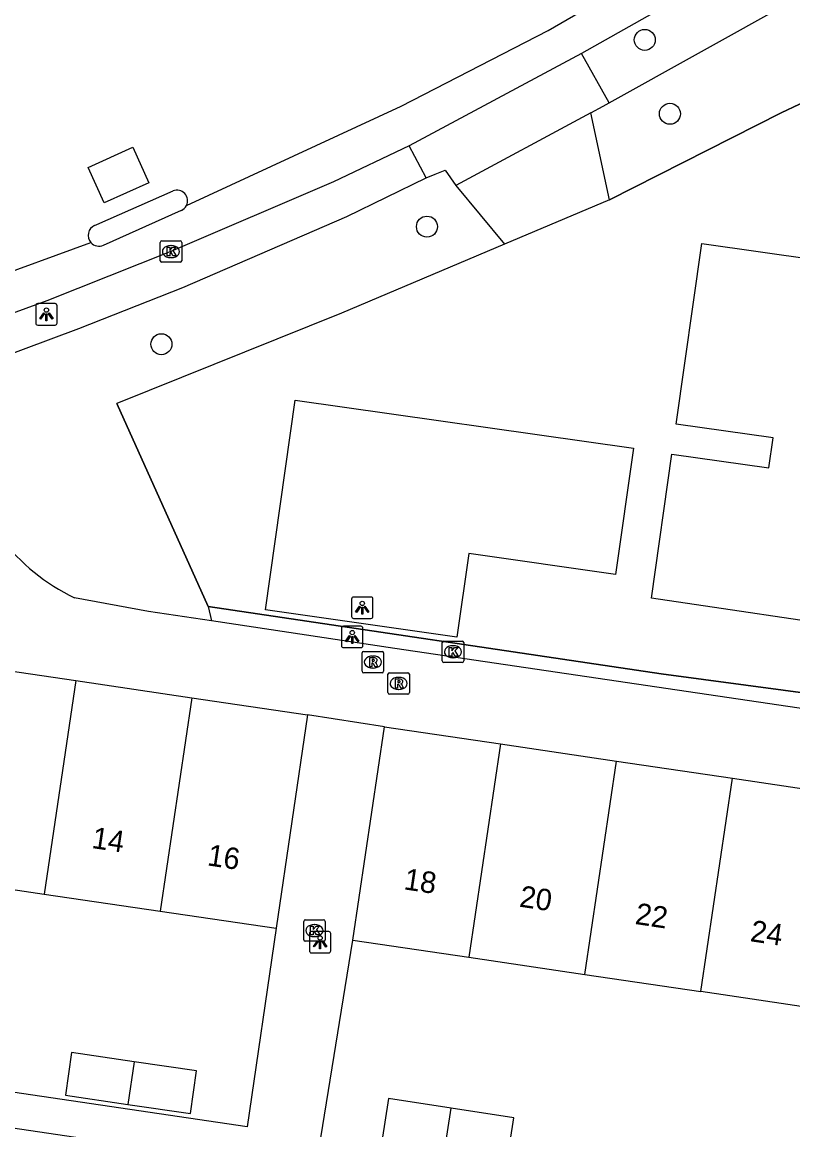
# Model space of a CAD drawing. Extents: x 164150 to 165261, y 382513 to 383432.
# Drawn here: x 164416.6 to 164452.5, y 383340.9 to 383392.6 of the extents above; entities that cross this region are included whole.
import ezdxf

# ---------------------------------------------------------------- set-up
doc = ezdxf.new("R2010")
doc.units = 0
for name, color, linetype in [('IMGEO_Boom', 7, 'Continuous'), ('IMGEO_Groenvoorziening', 7, 'Continuous'), ('IMGEO_Hek', 7, 'Continuous'), ('IMGEO_Kolk', 7, 'Continuous'), ('IMGEO_Lichtpunt', 7, 'Continuous'), ('IMGEO_Pand', 7, 'Continuous'), ('IMGEO_Pand_nummerreeks', 7, 'Continuous'), ('IMGEO_Rijbaan_lokaal_gesloten', 7, 'Continuous'), ('IMGEO_Rioolput', 7, 'Continuous'), ('IMGEO_Voetpad_open', 7, 'Continuous')]:
    doc.layers.add(name, color=color, linetype=linetype)

msp = doc.modelspace()

# ---------------------------------------------------------------- linework, layer by layer
at = {"layer": 'IMGEO_Boom'}
for centre in [(164445.636, 383391.73), (164446.809, 383388.287), (164435.49, 383383.028), (164423.12, 383377.55)]:
    msp.add_circle(centre, 0.489, dxfattribs=at)
at = {"layer": 'IMGEO_Groenvoorziening'}
for points in [[(164495.205, 383395.312), (164485.846, 383406.541), (164475.669, 383398.705), (164457.962, 383391.157), (164451.983, 383388.33), (164443.993, 383384.279)], [(164439.097, 383382.204), (164431.513, 383378.99), (164421.044, 383374.785), (164425.292, 383365.326)], [(164425.292, 383365.326), (164446.405, 383362.194), (164456.026, 383360.895), (164526.656, 383350.3)], [(164425.292, 383365.326), (164425.46, 383364.655)]]:
    msp.add_lwpolyline(points, dxfattribs=at)
at = {"layer": 'IMGEO_Hek'}
for points in [[(164443.993, 383384.279), (164451.983, 383388.33), (164457.962, 383391.157), (164475.669, 383398.705), (164485.846, 383406.541)], [(164439.097, 383382.204), (164431.513, 383378.99)], [(164431.513, 383378.99), (164421.044, 383374.785)], [(164425.292, 383365.326), (164421.044, 383374.785)], [(164526.656, 383350.3), (164456.026, 383360.895), (164446.405, 383362.194), (164425.292, 383365.326)]]:
    msp.add_lwpolyline(points, dxfattribs=at)
at = {"layer": 'IMGEO_Kolk'}
for p, q in [((164423.064, 383381.441), (164423.064, 383382.293)), ((164423.139, 383382.367), (164423.991, 383382.367)), ((164423.552, 383382.147), (164423.577, 383382.147)), ((164424.065, 383382.293), (164424.065, 383381.441)), ((164423.575, 383381.587), (164423.55, 383381.587)), ((164423.991, 383381.367), (164423.139, 383381.367)), ((164436.202, 383362.793), (164436.202, 383363.645)), ((164436.277, 383363.719), (164437.129, 383363.719)), ((164436.69, 383363.499), (164436.715, 383363.499)), ((164437.203, 383363.645), (164437.203, 383362.793)), ((164436.713, 383362.939), (164436.688, 383362.939)), ((164437.129, 383362.719), (164436.277, 383362.719)), ((164429.748, 383349.803), (164429.748, 383350.655)), ((164429.823, 383350.729), (164430.675, 383350.729)), ((164430.236, 383350.509), (164430.261, 383350.509)), ((164430.749, 383350.655), (164430.749, 383349.803)), ((164430.259, 383349.949), (164430.234, 383349.949)), ((164430.675, 383349.729), (164429.823, 383349.729))]:
    msp.add_line(p, q, dxfattribs=at)
for points in [[(164423.064, 383381.441), (164423.064, 383382.293)], [(164423.139, 383382.367), (164423.991, 383382.367)], [(164423.385, 383382.067), (164423.508, 383382.067), (164423.508, 383381.916), (164423.638, 383382.067), (164423.802, 383382.067), (164423.656, 383381.916), (164423.809, 383381.667), (164423.657, 383381.667), (164423.572, 383381.831), (164423.508, 383381.764), (164423.508, 383381.667), (164423.385, 383381.667), (164423.385, 383382.067)], [(164424.065, 383382.293), (164424.065, 383381.441)], [(164423.991, 383381.367), (164423.139, 383381.367)], [(164436.202, 383362.793), (164436.202, 383363.645)], [(164436.277, 383363.719), (164437.129, 383363.719)], [(164436.523, 383363.419), (164436.646, 383363.419), (164436.646, 383363.268), (164436.776, 383363.419), (164436.94, 383363.419), (164436.794, 383363.268), (164436.947, 383363.019), (164436.795, 383363.019), (164436.71, 383363.183), (164436.646, 383363.116), (164436.646, 383363.019), (164436.523, 383363.019), (164436.523, 383363.419)], [(164437.203, 383363.645), (164437.203, 383362.793)], [(164437.129, 383362.719), (164436.277, 383362.719)], [(164429.748, 383349.803), (164429.748, 383350.655)], [(164429.823, 383350.729), (164430.675, 383350.729)], [(164430.749, 383350.655), (164430.749, 383349.803)], [(164430.069, 383350.429), (164430.192, 383350.429), (164430.192, 383350.278), (164430.322, 383350.429), (164430.486, 383350.429), (164430.34, 383350.278), (164430.493, 383350.029), (164430.341, 383350.029), (164430.256, 383350.193), (164430.192, 383350.126), (164430.192, 383350.029), (164430.069, 383350.029), (164430.069, 383350.429)], [(164430.675, 383349.729), (164429.823, 383349.729)]]:
    msp.add_lwpolyline(points, dxfattribs=at)
for centre, start, end in [((164423.141, 383382.291), 91.552, 178.448), ((164423.141, 383382.291), 91.552, 178.448), ((164423.989, 383382.291), 1.552, 88.448), ((164423.989, 383382.291), 1.552, 88.448), ((164423.141, 383381.443), 181.552, 268.448), ((164423.141, 383381.443), 181.552, 268.448), ((164423.989, 383381.443), 271.552, 358.448), ((164423.989, 383381.443), 271.552, 358.448), ((164436.279, 383363.643), 91.552, 178.448), ((164436.279, 383363.643), 91.552, 178.448), ((164437.127, 383363.643), 1.552, 88.448), ((164437.127, 383363.643), 1.552, 88.448), ((164436.279, 383362.795), 181.552, 268.448), ((164436.279, 383362.795), 181.552, 268.448), ((164437.127, 383362.795), 271.552, 358.448), ((164437.127, 383362.795), 271.552, 358.448), ((164429.825, 383350.653), 91.552, 178.448), ((164429.825, 383350.653), 91.552, 178.448), ((164430.673, 383350.653), 1.552, 88.448), ((164430.673, 383350.653), 1.552, 88.448), ((164429.825, 383349.805), 181.552, 268.448), ((164429.825, 383349.805), 181.552, 268.448), ((164430.673, 383349.805), 271.552, 358.448), ((164430.673, 383349.805), 271.552, 358.448)]:
    msp.add_arc(centre, 0.0765, start, end, dxfattribs=at)
for centre, major_axis, ratio, start_param, end_param in [((164423.551, 383381.867), (-0.387, 0.002), 0.722429, 4.712389, 7.853982), ((164423.576, 383381.867), (-0.39, 0.002), 0.717154, 1.570796, 4.712389), ((164436.689, 383363.219), (-0.387, 0.002), 0.722429, 4.712389, 7.853982), ((164436.714, 383363.219), (-0.39, 0.002), 0.717154, 1.570796, 4.712389), ((164430.235, 383350.229), (-0.387, 0.002), 0.722429, 4.712389, 7.853982), ((164430.26, 383350.229), (-0.39, 0.002), 0.717154, 1.570796, 4.712389)]:
    msp.add_ellipse(centre, major_axis=major_axis, ratio=ratio, start_param=start_param, end_param=end_param, dxfattribs=at)
at = {"layer": 'IMGEO_Lichtpunt'}
for p, q in [((164417.264, 383379.344), (164417.264, 383378.537)), ((164417.264, 383379.344), (164417.264, 383378.537)), ((164418.166, 383379.439), (164417.358, 383379.439)), ((164418.166, 383379.439), (164417.358, 383379.439)), ((164418.26, 383378.537), (164418.26, 383379.344)), ((164418.26, 383378.537), (164418.26, 383379.344)), ((164417.358, 383378.443), (164418.166, 383378.443)), ((164417.358, 383378.443), (164418.166, 383378.443)), ((164431.977, 383365.674), (164431.977, 383364.867)), ((164431.977, 383365.674), (164431.977, 383364.867)), ((164432.879, 383365.769), (164432.071, 383365.769)), ((164432.879, 383365.769), (164432.071, 383365.769)), ((164432.973, 383364.867), (164432.973, 383365.674)), ((164432.973, 383364.867), (164432.973, 383365.674)), ((164432.412, 383364.409), (164431.604, 383364.409)), ((164432.412, 383364.409), (164431.604, 383364.409)), ((164432.071, 383364.773), (164432.879, 383364.773)), ((164432.071, 383364.773), (164432.879, 383364.773)), ((164431.51, 383364.314), (164431.51, 383363.507)), ((164431.51, 383364.314), (164431.51, 383363.507)), ((164432.506, 383363.507), (164432.506, 383364.314)), ((164432.506, 383363.507), (164432.506, 383364.314)), ((164431.604, 383363.413), (164432.412, 383363.413)), ((164431.604, 383363.413), (164432.412, 383363.413)), ((164430.015, 383350.09), (164430.015, 383349.283)), ((164430.015, 383350.09), (164430.015, 383349.283)), ((164430.917, 383350.185), (164430.109, 383350.185)), ((164430.917, 383350.185), (164430.109, 383350.185)), ((164431.011, 383349.283), (164431.011, 383350.09)), ((164431.011, 383349.283), (164431.011, 383350.09)), ((164430.109, 383349.189), (164430.917, 383349.189)), ((164430.109, 383349.189), (164430.917, 383349.189))]:
    msp.add_line(p, q, dxfattribs=at)
for points in [[(164417.638, 383379.008), (164417.677, 383378.98), (164417.489, 383378.718), (164417.451, 383378.745), (164417.638, 383379.008)], [(164417.74, 383378.96), (164417.787, 383378.96), (164417.787, 383378.638), (164417.74, 383378.638), (164417.74, 383378.96)], [(164417.85, 383378.98), (164417.888, 383379.007), (164418.075, 383378.745), (164418.036, 383378.717), (164417.85, 383378.98)], [(164432.351, 383365.338), (164432.39, 383365.31), (164432.202, 383365.048), (164432.164, 383365.075), (164432.351, 383365.338)], [(164432.453, 383365.29), (164432.5, 383365.29), (164432.5, 383364.968), (164432.453, 383364.968), (164432.453, 383365.29)], [(164432.563, 383365.31), (164432.601, 383365.337), (164432.788, 383365.075), (164432.749, 383365.047), (164432.563, 383365.31)], [(164431.884, 383363.978), (164431.923, 383363.95), (164431.735, 383363.688), (164431.697, 383363.715), (164431.884, 383363.978)], [(164431.986, 383363.93), (164432.033, 383363.93), (164432.033, 383363.608), (164431.986, 383363.608), (164431.986, 383363.93)], [(164432.096, 383363.95), (164432.134, 383363.977), (164432.321, 383363.715), (164432.282, 383363.687), (164432.096, 383363.95)], [(164430.389, 383349.754), (164430.428, 383349.726), (164430.24, 383349.464), (164430.202, 383349.491), (164430.389, 383349.754)], [(164430.491, 383349.706), (164430.538, 383349.706), (164430.538, 383349.384), (164430.491, 383349.384), (164430.491, 383349.706)], [(164430.601, 383349.726), (164430.639, 383349.753), (164430.826, 383349.491), (164430.787, 383349.463), (164430.601, 383349.726)]]:
    msp.add_lwpolyline(points, dxfattribs=at)
for centre in [(164417.763, 383379.142), (164432.476, 383365.472), (164432.009, 383364.112), (164430.514, 383349.888)]:
    msp.add_circle(centre, 0.0994, dxfattribs=at)
for centre, start, end in [((164417.358, 383379.344), 90, 180), ((164417.358, 383379.344), 90, 180), ((164418.166, 383379.344), 0, 90), ((164418.166, 383379.344), 0, 90), ((164417.358, 383378.537), 180, 270), ((164417.358, 383378.537), 180, 270), ((164418.166, 383378.537), 270, 0), ((164418.166, 383378.537), 270, 360), ((164432.071, 383365.674), 90, 180), ((164432.071, 383365.674), 90, 180), ((164432.879, 383365.674), 0, 90), ((164432.879, 383365.674), 0, 90), ((164431.604, 383364.314), 90, 180), ((164431.604, 383364.314), 90, 180), ((164432.071, 383364.867), 180, 270), ((164432.071, 383364.867), 180, 270), ((164432.412, 383364.314), 0, 90), ((164432.412, 383364.314), 0, 90), ((164432.879, 383364.867), 270, 0), ((164432.879, 383364.867), 270, 360), ((164431.604, 383363.507), 180, 270), ((164431.604, 383363.507), 180, 270), ((164432.412, 383363.507), 270, 0), ((164432.412, 383363.507), 270, 360), ((164430.109, 383350.09), 90, 180), ((164430.109, 383350.09), 90, 180), ((164430.917, 383350.09), 0, 90), ((164430.917, 383350.09), 0, 90), ((164430.109, 383349.283), 180, 270), ((164430.109, 383349.283), 180, 270), ((164430.917, 383349.283), 270, 0), ((164430.917, 383349.283), 270, 360)]:
    msp.add_arc(centre, 0.0946, start, end, dxfattribs=at)
at = {"layer": 'IMGEO_Pand'}
for points in [[(164498.259, 383358.532), (164472.187, 383362.422), (164472.098, 383361.829), (164466.687, 383362.633), (164467.658, 383369.162), (164457.191, 383370.718), (164456.22, 383364.19), (164445.943, 383365.718), (164446.895, 383372.431), (164451.415, 383371.79), (164451.612, 383373.18), (164447.093, 383373.821), (164448.288, 383382.248), (164464.263, 383379.981), (164465.397, 383387.967), (164470.329, 383387.267), (164471.063, 383392.438), (164476.192, 383391.71)], [(164444.272, 383366.824), (164437.44, 383367.793), (164436.888, 383363.902), (164427.967, 383365.167), (164429.354, 383374.939), (164445.106, 383372.705), (164444.272, 383366.824)], [(164413.728, 383362.671), (164419.13, 383361.874)], [(164419.13, 383361.874), (164417.663, 383351.931)], [(164419.13, 383361.874), (164424.531, 383361.077)], [(164424.531, 383361.077), (164423.065, 383351.135)], [(164424.531, 383361.077), (164429.933, 383360.28)], [(164429.933, 383360.28), (164428.467, 383350.338)], [(164432.042, 383349.787), (164433.514, 383359.729)], [(164433.514, 383359.729), (164438.915, 383358.929)], [(164438.915, 383358.929), (164437.443, 383348.987)], [(164438.915, 383358.929), (164444.316, 383358.129)], [(164442.844, 383348.187), (164444.316, 383358.129)], [(164444.316, 383358.129), (164449.718, 383357.329)], [(164448.245, 383347.387), (164449.718, 383357.329)], [(164449.718, 383357.329), (164455.119, 383356.529)], [(164412.262, 383352.728), (164417.663, 383351.931)], [(164417.663, 383351.931), (164423.065, 383351.135)], [(164423.065, 383351.135), (164428.467, 383350.338)], [(164432.042, 383349.787), (164437.443, 383348.987)], [(164437.443, 383348.987), (164442.844, 383348.187)], [(164442.844, 383348.187), (164448.245, 383347.387)], [(164453.646, 383346.588), (164448.245, 383347.387)], [(164421.849, 383344.118), (164418.938, 383344.544), (164418.647, 383342.553), (164421.558, 383342.127)], [(164421.558, 383342.127), (164424.468, 383341.701), (164424.759, 383343.692), (164421.849, 383344.118)], [(164421.849, 383344.118), (164421.558, 383342.127)], [(164436.622, 383341.954), (164433.706, 383342.41), (164433.393, 383340.407), (164436.308, 383339.951)], [(164436.308, 383339.951), (164436.622, 383341.954)], [(164436.308, 383339.951), (164439.224, 383339.495), (164439.537, 383341.498), (164436.622, 383341.954)]]:
    msp.add_lwpolyline(points, dxfattribs=at)
at = {"layer": 'IMGEO_Rijbaan_lokaal_gesloten'}
for points in [[(164424.287, 383384.014), (164434.282, 383388.647), (164441.136, 383392.174), (164450.74, 383397.743), (164455.439, 383399.809), (164461.26, 383402.185)], [(164451.009, 383395.796), (164442.692, 383391.095)], [(164442.692, 383391.095), (164434.664, 383386.795)], [(164434.664, 383386.795), (164431.134, 383385.12), (164423.565, 383381.867), (164417.783, 383379.568), (164412.246, 383377.557), (164405.377, 383375.292), (164399.239, 383373.497), (164393.394, 383372), (164385.372, 383370.275), (164379.217, 383369.164), (164364.147, 383366.805), (164355.96, 383365.609), (164347.021, 383364.613), (164333.574, 383363.59), (164329.584, 383363.288), (164324.642, 383362.347), (164322.532, 383361.699), (164314.821, 383358.779), (164313.606, 383358.425)], [(164422.536, 383385.071), (164420.457, 383384.136), (164419.713, 383385.791), (164421.793, 383386.725), (164422.536, 383385.071)], [(164420.009, 383383.079), (164420.115, 383383.125), (164423.664, 383384.69)], [(164420.422, 383382.17), (164424.05, 383383.788)], [(164313.12, 383360.215), (164324.281, 383363.805), (164329.441, 383365.032), (164345.601, 383366.353), (164363.616, 383368.567), (164384.72, 383372.013), (164391.019, 383373.335), (164397.192, 383374.879), (164403.181, 383376.603), (164414.799, 383380.452), (164419.832, 383382.287)]]:
    msp.add_lwpolyline(points, dxfattribs=at)
for centre, radius, start, end in [((164423.851, 383384.237), 0.49, 332.9343, 112.3928), ((164423.847, 383384.238), 0.494, 294.2781, 332.9999), ((164420.204, 383382.62), 0.499, 113.0293, 221.7752), ((164420.204, 383382.616), 0.496, 221.4883, 296.0787)]:
    msp.add_arc(centre, radius, start, end, dxfattribs=at)
at = {"layer": 'IMGEO_Rioolput'}
for p, q in [((164432.472, 383362.313), (164432.472, 383363.165)), ((164432.547, 383363.239), (164433.399, 383363.239)), ((164432.96, 383363.019), (164432.985, 383363.019)), ((164433.473, 383363.165), (164433.473, 383362.313)), ((164432.983, 383362.459), (164432.958, 383362.459)), ((164433.399, 383362.239), (164432.547, 383362.239)), ((164433.671, 383361.319), (164433.671, 383362.171)), ((164433.746, 383362.245), (164434.598, 383362.245)), ((164434.159, 383362.025), (164434.184, 383362.025)), ((164434.672, 383362.171), (164434.672, 383361.319)), ((164434.182, 383361.465), (164434.157, 383361.465)), ((164434.598, 383361.245), (164433.746, 383361.245))]:
    msp.add_line(p, q, dxfattribs=at)
for points in [[(164432.472, 383362.313), (164432.472, 383363.165)], [(164432.547, 383363.239), (164433.399, 383363.239)], [(164433.061, 383362.937), (164432.809, 383362.939), (164432.809, 383362.539)], [(164432.987, 383362.858), (164432.933, 383362.858), (164432.933, 383362.777)], [(164433.473, 383363.165), (164433.473, 383362.313)], [(164432.809, 383362.539), (164432.933, 383362.539), (164432.933, 383362.701), (164432.944, 383362.701)], [(164432.933, 383362.777), (164432.985, 383362.777)], [(164432.991, 383362.672), (164433.062, 383362.539), (164433.202, 383362.539), (164433.137, 383362.665)], [(164433.399, 383362.239), (164432.547, 383362.239)], [(164433.671, 383361.319), (164433.671, 383362.171)], [(164433.746, 383362.245), (164434.598, 383362.245)], [(164434.26, 383361.943), (164434.008, 383361.945), (164434.008, 383361.545)], [(164434.186, 383361.864), (164434.132, 383361.864), (164434.132, 383361.783)], [(164434.672, 383362.171), (164434.672, 383361.319)], [(164434.008, 383361.545), (164434.132, 383361.545), (164434.132, 383361.707), (164434.143, 383361.707)], [(164434.132, 383361.783), (164434.184, 383361.783)], [(164434.19, 383361.678), (164434.261, 383361.545), (164434.401, 383361.545), (164434.336, 383361.671)], [(164434.598, 383361.245), (164433.746, 383361.245)]]:
    msp.add_lwpolyline(points, dxfattribs=at)
for centre, radius, start, end in [((164432.549, 383363.163), 0.0765, 91.552, 178.448), ((164432.549, 383363.163), 0.0765, 91.552, 178.448), ((164432.993, 383362.762), 0.0964, 77.0061, 93.1865), ((164433.007, 383362.819), 0.0378, 276.6634, 79.6772), ((164433.06, 383362.827), 0.109, 350.3612, 89.416), ((164433.397, 383363.163), 0.0765, 1.552, 88.448), ((164433.397, 383363.163), 0.0765, 1.552, 88.448), ((164432.549, 383362.315), 0.0765, 181.552, 268.448), ((164432.549, 383362.315), 0.0765, 181.552, 268.448), ((164432.943, 383362.648), 0.0533, 26.0293, 88.6989), ((164432.969, 383362.966), 0.19, 274.7715, 282.9687), ((164433.058, 383362.827), 0.112, 277.5842, 350.9817), ((164433.042, 383362.612), 0.108, 29.5134, 73.7905), ((164433.397, 383362.315), 0.0765, 271.552, 358.448), ((164433.397, 383362.315), 0.0765, 271.552, 358.448), ((164433.748, 383362.169), 0.0765, 91.552, 178.448), ((164433.748, 383362.169), 0.0765, 91.552, 178.448), ((164434.192, 383361.768), 0.0964, 77.0061, 93.1865), ((164434.206, 383361.825), 0.0378, 276.6634, 79.6772), ((164434.259, 383361.833), 0.109, 350.3612, 89.416), ((164434.257, 383361.833), 0.112, 277.5842, 350.9817), ((164434.596, 383362.169), 0.0765, 1.552, 88.448), ((164434.596, 383362.169), 0.0765, 1.552, 88.448), ((164433.748, 383361.321), 0.0765, 181.552, 268.448), ((164433.748, 383361.321), 0.0765, 181.552, 268.448), ((164434.142, 383361.654), 0.0533, 26.0293, 88.6989), ((164434.168, 383361.972), 0.19, 274.7715, 282.9687), ((164434.241, 383361.618), 0.108, 29.5134, 73.7905), ((164434.596, 383361.321), 0.0765, 271.552, 358.448), ((164434.596, 383361.321), 0.0765, 271.552, 358.448)]:
    msp.add_arc(centre, radius, start, end, dxfattribs=at)
for centre, major_axis, ratio, start_param, end_param in [((164432.959, 383362.739), (-0.387, 0.002), 0.722429, 4.712389, 7.853982), ((164432.984, 383362.739), (-0.39, 0.002), 0.717154, 1.570796, 4.712389), ((164434.158, 383361.745), (-0.387, 0.002), 0.722429, 4.712389, 7.853982), ((164434.183, 383361.745), (-0.39, 0.002), 0.717154, 1.570796, 4.712389)]:
    msp.add_ellipse(centre, major_axis=major_axis, ratio=ratio, start_param=start_param, end_param=end_param, dxfattribs=at)
at = {"layer": 'IMGEO_Voetpad_open'}
for points in [[(164443.98, 383388.794), (164452.441, 383393.51)], [(164443.98, 383388.794), (164442.692, 383391.095)], [(164443.124, 383388.333), (164443.694, 383388.64), (164443.98, 383388.794)], [(164443.124, 383388.333), (164436.84, 383384.948)], [(164443.993, 383384.279), (164443.124, 383388.333)], [(164435.447, 383385.302), (164434.664, 383386.795)], [(164435.447, 383385.302), (164435.88, 383385.472), (164436.341, 383385.654), (164436.84, 383384.948)], [(164411.731, 383375.499), (164412.816, 383375.869), (164419.281, 383378.282), (164424.123, 383380.189), (164431.753, 383383.495), (164435.447, 383385.302)], [(164436.84, 383384.948), (164439.097, 383382.204)], [(164443.993, 383384.279), (164439.097, 383382.204)], [(164425.46, 383364.655), (164422.515, 383365.1), (164419.068, 383365.739)], [(164526.587, 383349.71), (164433.986, 383363.368), (164425.46, 383364.655)], [(164433.514, 383359.729), (164429.933, 383360.28)], [(164428.467, 383350.338), (164427.117, 383341.092), (164383.799, 383347.483)], [(164486.005, 383341.796), (164484.639, 383332.608), (164430.539, 383340.579), (164432.042, 383349.787)], [(164390.731, 383344.808), (164424.372, 383339.822)]]:
    msp.add_lwpolyline(points, dxfattribs=at)
msp.add_arc((164423.021, 383374.073), 9.224, 216.9511, 244.6217, dxfattribs=at)

# ---------------------------------------------------------------- texts
at = {"layer": 'IMGEO_Pand_nummerreeks'}
for s, rotation, p in [('14', 351.4744, (164419.84, 383354.08)), ('16', 351.4744, (164425.222, 383353.273)), ('18', 351.4801, (164434.379, 383352.154)), ('20', 351.4801, (164439.759, 383351.348)), ('22', 351.4801, (164445.15, 383350.54)), ('24', 351.4801, (164450.513, 383349.737))]:
    msp.add_text(s, height=1, rotation=rotation, dxfattribs=at).set_placement(p)

doc.saveas('drawing.dxf')
